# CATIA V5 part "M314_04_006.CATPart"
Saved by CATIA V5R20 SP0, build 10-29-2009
Part number: M314_04_006
Source: Unknown
Property "ARTICLENO": "M314-04-006"
Property "B": "35.000"
Property "BOMINFO": "M314-04-006"
Property "CODE": "M314-04-006"
Property "D": "8.000"
Property "FINALFORCE": "78.4 (8)"
Property "INITIALFORCE": "26.4 (2.7)"
Property "K": "10.000"
Property "L": "60.000"
Property "LINA": "M314-04-006"
Property "M": "M16x2.0"
Property "NB": "M314-04-006"
Property "NBSYN": "$CODE."
Property "NN": "M314-04"
Property "NT": "Spring Plunger"
Property "SUPPLIER": "CF"
Property "SW": "5.000"
Bounding box of the stored display mesh (mm): x -8 to 8, y 0 to 70, z -8 to 8
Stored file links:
  C:\Users\Utente\Desktop\3D files M314\M314_04_006.CATPart
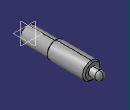
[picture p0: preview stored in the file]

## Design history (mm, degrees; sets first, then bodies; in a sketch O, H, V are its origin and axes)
Body1 "Geometry.1" (main body)
  Solid1 "M314_04_006.catpart": solid without history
